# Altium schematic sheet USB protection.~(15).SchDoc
size A3; SheetNumber: 7; SheetTotal: 7
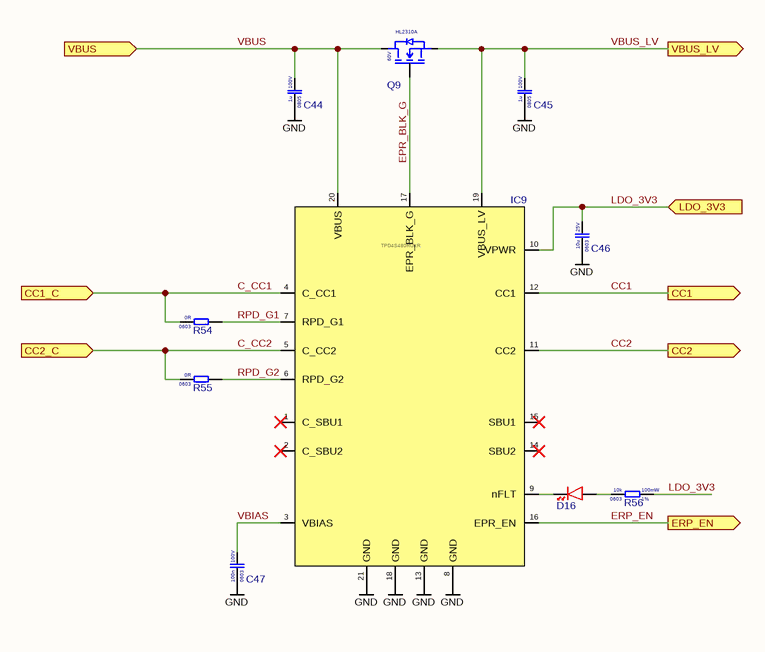
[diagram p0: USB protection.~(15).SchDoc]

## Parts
C44  Voltage Rating: 100V  Case Code (Imperial): 0805  Capacitance: 1u  [Cap_0805]  (hidden comment: CC0805KKX7R0BB105)
C45  Voltage Rating: 100V  Case Code (Imperial): 0805  Capacitance: 1u  [Cap_0805]  (hidden comment: CC0805KKX7R0BB105)
C46  Voltage Rating: 25V  Case Code (Imperial): 0603  Capacitance: 10u  [CAP 0603]  (hidden comment: CL10A106MA8NRNC)
C47  Voltage Rating: 100V  Case Code (Imperial): 0603  Capacitance: 100n  [CAP 0603]  (hidden comment: CC0603KRX7R0BB104)
D16  XL-1608SURC-06  [DIODE_0603]  (value not drawn)
IC9  TPD4S480RUKR  [WQFN (20)]
Q9  Voltage: 60V  [SOT-23 GSD]  (hidden comment: HL2310A)
R54  Resistance: 0R  Case Code (Imperial): 0603  [RES_0603]  (hidden comment: 0603WAF0000T5E)
R55  Resistance: 0R  Case Code (Imperial): 0603  [RES_0603]  (hidden comment: 0603WAF0000T5E)
R56  Resistance Tolerance: 1%  Resistance: 10k  Power Rating: 100mW  Case Code (Imperial): 0603  [RES_0603]  (hidden comment: 0603WAF1002T5E)

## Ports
CC1 (out, see Arhitecture[3B], USB PD[3C]), CC1_C (in, see Arhitecture[2B]), CC2 (out, see Arhitecture[3B], USB PD[3C]), CC2_C (in, see Arhitecture[2B]), ERP_EN (out, see Arhitecture[3B], USB PD[5B]), LDO_3V3 (in, see Arhitecture[3B], USB PD[3C]), VBUS (in, see Arhitecture[2B], Power path switch[3B]), VBUS_LV (out, see Arhitecture[3B], USB PD[3B])

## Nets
GND: C44.1 C45.1 C46.1 C47.1 IC9.8(GND) IC9.13(GND) IC9.18(GND) IC9.21(GND)
C_CC1: IC9.4(C_CC1) R54.1 ; port CC1_C
C_CC2: IC9.5(C_CC2) R55.1 ; port CC2_C
CC1: IC9.12(CC1) ; port CC1
CC2: IC9.11(CC2) ; port CC2
EPR_BLK_G: IC9.17(EPR_BLK_G) Q9.G
ERP_EN: IC9.16(EPR_EN) ; port ERP_EN
LDO_3V3: C46.2 IC9.10(VPWR) R56.2 ; port LDO_3V3
RPD_G1: IC9.7(RPD_G1) R54.2
RPD_G2: IC9.6(RPD_G2) R55.2
VBIAS: C47.2 IC9.3(VBIAS)
VBUS: C44.2 IC9.20(VBUS) Q9.D ; port VBUS
VBUS_LV: C45.2 IC9.19(VBUS_LV) Q9.S ; port VBUS_LV
NetD16_A: D16.A R56.1
NetD16_K: D16.K IC9.9(nFLT)

Not connected (* = marked no-connect by the designer): IC9 1(C_SBU1)* 2(C_SBU2)* 14(SBU2)* 15(SBU1)*

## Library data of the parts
C44 C45 = CC0805KKX7R0BB105: Cap 1uF 100V 0805 X7R; Manufacturer: Yageo
C46 = CL10A106MA8NRNC: Cap 10uF 25V 0603 X5R; Manufacturer: Samsung
C47 = CC0603KRX7R0BB104: Cap 100nF 100V 0603 X7R; Manufacturer: YAGEO
D16 = XL-1608SURC-06: LED Red 0603 25mA; Manufacturer: Xinglight
IC9 = TPD4S480RUKR: USB PD protection IC; Manufacturer: Texas Instruments
Q9 = HL2310A: nMOS 60V 3A SOT-23; Manufacturer: hongjiacheng
R54 R55 = 0603WAF0000T5E: Res 0R 0603 1% 100mW 75V; Manufacturer: UNI-ROYAL
R56 = 0603WAF1002T5E: Res 10k 0603 1% 100mW 75V; Manufacturer: Uni-Royal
